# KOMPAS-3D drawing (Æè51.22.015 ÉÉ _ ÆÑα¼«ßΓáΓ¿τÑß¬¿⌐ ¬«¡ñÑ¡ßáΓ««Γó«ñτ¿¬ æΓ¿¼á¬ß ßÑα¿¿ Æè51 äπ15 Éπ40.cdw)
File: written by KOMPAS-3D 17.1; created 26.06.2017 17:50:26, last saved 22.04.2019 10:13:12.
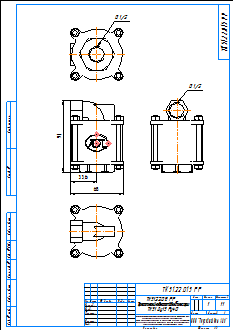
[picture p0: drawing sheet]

Sheet 1: A3, portrait

Title block, sheet 1: name: ТК51.22.015 РР _ / Термостатический конденсатоотводчик Стимакс серии / ТК51 Ду15 Ру40; designation: ТК51.22.015 РР; material: Внимание! Данный продукт является объектом авторского права ООО «Торговый Дом АДЛ». / Запрещается изменение, копирование, распространение / (в том числе путем копирования на другие сайты и ресурсы в Интернете) / или любое иное использование информации и объектов без предварительного / согласия правообладателя (ООО «Торговый Дом АДЛ»).; mass: 1; sheets: 1; organisation: ООО "Торговый дом АДЛ"; sheet format: A3; stored path: \\adlc.lan\data\АДЛ_ПКД\3D-модели\ADL production\Конденсатоотводчики СТИМАКС\Капсульные\Серии ТК51\KOMPAS 2D\ТК51.22.015 РР _ Термостатический конденсатоотводчик Стимакс серии ТК51 Ду15 Ру40.cdw

Views: Вид 1, Проекционный вид 3, Проекционный вид 4
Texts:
  Klimkovich
  ADL
Dimensions and other numbers on the sheet: 68; 33,6; 91; 1:1; 1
